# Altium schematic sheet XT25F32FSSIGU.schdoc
size 127 x 101 mm
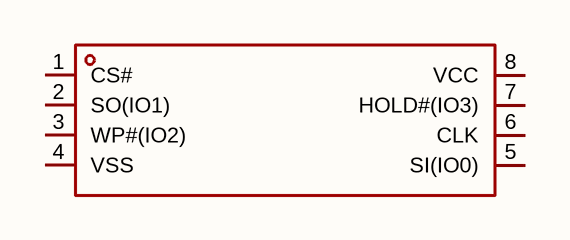
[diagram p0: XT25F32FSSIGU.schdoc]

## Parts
U?  xt25f32fssigu  [SOP-8_L5.3-W5.3-P1.27-LS7.9-BL]  (value not drawn)

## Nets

Not connected (* = marked no-connect by the designer): U? 1(CS#) 2(SO(IO1)) 3(WP#(IO2)) 4(VSS) 5(SI(IO0)) 6(CLK) 7(HOLD#(IO3)) 8(VCC)

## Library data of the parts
U? = xt25f32fssigu: 接口类型:SPI;存储容量:32Mbit;时钟频率(fc):133MHz;; Manufacturer: XTX(芯天下); AddInBom: yes; ModelId: 72eaeed142424588879d6a198b07ab72; ModelTransform: 207.67675,311.023,0,0,0,0,0,0,0; Interface: SPI; Memory Size: 32Mbit; Clock Frequency: 133MHz; Voltage - Supply: 2.7V~3.6V; Standby Supply Current: 0.3uA; Program / Erase Cycles: 100000次; Page Programming Time (Tpp): 400us; Block Erase Time(tBE): 150ms; Data Retention - TDR (Year): 20年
